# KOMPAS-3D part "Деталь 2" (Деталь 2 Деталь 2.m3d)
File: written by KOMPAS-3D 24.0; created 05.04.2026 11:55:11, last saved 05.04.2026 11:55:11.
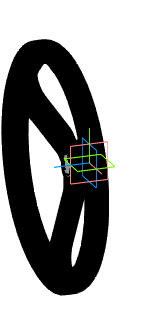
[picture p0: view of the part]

Document properties: Автор: R2D2; Полное имя файла: E:\Работа\Зайцев\Аксессуары для пневмоприводов\Ручной дублер DN.ru\MON4-1200-T54-ISO Ручной дублер DN.ru\исходные материалы\Деталь 2 Деталь 2.m3d

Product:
- Body: Твердое тело1  | qty 1
- Part/product: Деталь 2
    additional columns: Типовые

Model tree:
1. Твердое тело1  (labels: Твердое тело1)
